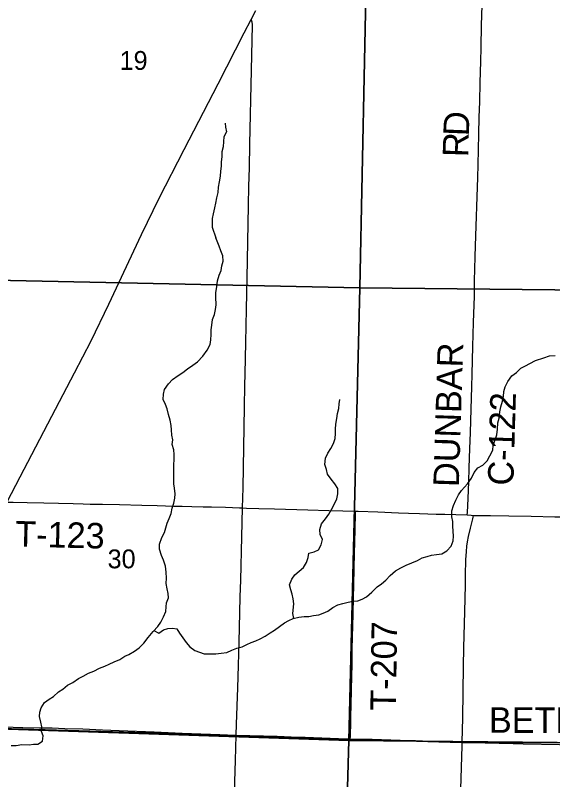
# Model space of a CAD drawing. Extents: x 1584893 to 1934202, y 663575 to 1091909.
# Drawn here: x 1777861 to 1784167, y 904934 to 913906 of the extents above; entities that cross this region are included whole.
import ezdxf

# ---------------------------------------------------------------- set-up
doc = ezdxf.new("R2010")
doc.units = 0
for name, color, linetype in [('GM_X_County_Road', 7, 'Continuous'), ('GM_X_County_Road_Text', 7, 'Continuous'), ('GM_X_Minor_River', 7, 'Continuous'), ('GM_X_Section', 7, 'Continuous'), ('GM_X_Section_Text', 7, 'Continuous'), ('GM_X_State_Route', 7, 'Continuous'), ('GM_X_Township', 7, 'Continuous'), ('GM_X_Township_Road', 7, 'Continuous'), ('GM_X_Township_Road_Text', 7, 'Continuous')]:
    doc.layers.add(name, color=color, linetype=linetype)

msp = doc.modelspace()

# ---------------------------------------------------------------- linework, layer by layer
at = {"layer": 'GM_X_County_Road'}
for points in [[(1783164.7, 908041.5), (1783166.1, 908070.2), (1783173.9, 908233.5), (1783181.1, 908430.1), (1783187.4, 908594), (1783195.5, 908823.4), (1783201.6, 909003.7), (1783205.7, 909151.2), (1783216, 909544.7), (1783220.3, 909692.2), (1783230.6, 910020.1), (1783237.7, 910298.8), (1783247.2, 910610.3), (1783249.5, 910790.7), (1783256.9, 911069.3), (1783262.5, 911200.3), (1783269.7, 911429.8), (1783280.2, 911774.1), (1783286.9, 912003.5), (1783292, 912151.1), (1783300.6, 912511.8), (1783305.7, 912708.5), (1783311.6, 912888.8), (1783317.5, 913118.4), (1783322.6, 913364.2), (1783325.5, 913528.2), (1783332.5, 913790.4), (1783339.3, 914019.9)], [(1780527.7, 908123.4), (1780533.2, 908358.4), (1780550.5, 909310), (1780555.8, 909562.5), (1780558.7, 909698.8), (1780566.5, 910064.6), (1780572.7, 910458.3), (1780581.4, 910819.1), (1780597.5, 911672.2), (1780601.6, 911901.7), (1780607.5, 912114.8), (1780613, 912393.7), (1780632.6, 913263), (1780642.7, 913788.2), (1780642.5, 913803.8), (1780641.8, 913811.7), (1780640.6, 913818.2), (1780638.3, 913826.3), (1780635.5, 913835.1), (1780631.1, 913847.5), (1780627.3, 913857.9)], [(1780452.8, 905456.3), (1780456.8, 905587.7), (1780470.4, 906014), (1780479.3, 906276.3), (1780486, 906555.2), (1780490.6, 906718.8), (1780500.5, 907079.4), (1780505.7, 907276.1), (1780519.7, 907784.4), (1780527.7, 908123.4)], [(1783106.2, 905376.6), (1783112.6, 905659.8), (1783120.5, 906267.1), (1783124.2, 906480.3), (1783133.9, 906906.9), (1783143.3, 907218.6), (1783145, 907333.6), (1783149.2, 907513.9), (1783154.3, 907612.1), (1783160.2, 907677.2), (1783167.1, 907725.7), (1783179.1, 907790), (1783201, 907885.9), (1783228.9, 907997.2), (1783238.9, 908036.5)], [(1776762.7, 905586.7), (1776948.6, 905580.9), (1777375, 905566.6), (1777949, 905548.7), (1778145.8, 905544.4), (1778293.5, 905541.5), (1778441, 905536.8), (1778654.1, 905530), (1778883.5, 905520.4), (1779080.3, 905512.4), (1779490.1, 905496.3), (1779818, 905482.6), (1780260.6, 905464.3), (1780440.9, 905456.7), (1780452.8, 905456.3)], [(1780376.1, 902828), (1780381.5, 903062.1), (1780396.4, 903570.5), (1780425.1, 904538.1), (1780443.4, 905161.3), (1780452.8, 905456.3)], [(1780452.8, 905456.3), (1780932.9, 905443.9), (1781180.7, 905435.2), (1781260.8, 905432.4), (1781752.8, 905415.6), (1781792.1, 905414.8)], [(1781792.1, 905414.8), (1782048, 905408.7), (1782376, 905398.2), (1782556.3, 905392.9), (1782638.2, 905390.2), (1782790.1, 905385.1), (1782848.8, 905383.1), (1783048.1, 905378.4), (1783106.2, 905376.6)], [(1783090.4, 904823), (1783105.1, 905331.6), (1783106.2, 905376.6)], [(1783106.2, 905376.6), (1783376.2, 905369.1), (1783704.2, 905358.8), (1783818.9, 905355.3), (1784245.3, 905347.5), (1784688.3, 905345.7), (1784901.5, 905347.7), (1785246, 905353), (1785475.7, 905357), (1785981.6, 905365), (1786017, 905365.5), (1786328.7, 905372.4), (1786558.5, 905372.2), (1786903.1, 905372.1), (1787083.1, 905370.1), (1787086.6, 905369.8)]]:
    msp.add_lwpolyline(points, dxfattribs=at)
at = {"layer": 'GM_X_Minor_River'}
for points in [[(1780321.6, 912641.7), (1780326.7, 912591.6), (1780337.8, 912539.4), (1780308.9, 912477.8), (1780302, 912425.9), (1780301, 912363.9), (1780284, 912304.1), (1780283, 912244.1), (1780278, 912184.2), (1780277.2, 912134.1), (1780270.3, 912078.2), (1780265.3, 912016.2), (1780252.2, 911950.4), (1780243.2, 911890.5), (1780236.2, 911826.6), (1780221.1, 911762.8), (1780208.1, 911699), (1780197.2, 911645.2), (1780182.1, 911575.4), (1780169.2, 911521.5), (1780172.4, 911471.4), (1780169.5, 911419.5), (1780213.8, 911293.1)], [(1779693.9, 909041.2), (1779690.7, 909093.4), (1779677.6, 909155.7), (1779658.6, 909222.1), (1779643.6, 909288.5), (1779624.4, 909338.9), (1779597.3, 909397.4), (1779598.2, 909459.5), (1779612.9, 909513.4), (1779657.8, 909578.8), (1779706.5, 909630.2), (1779773.1, 909679.3), (1779825.5, 909714.6), (1779880, 909757.9), (1779942.5, 909801), (1779997, 909838.3), (1780059.9, 909905.5), (1780110.8, 909976.9), (1780147.7, 910040.5), (1780156.5, 910096.4), (1780159.4, 910158.5), (1780160.2, 910214.6), (1780167, 910270.6), (1780175.9, 910334.6), (1780196.7, 910394.4), (1780211.6, 910454.3), (1780218.3, 910506.3), (1780213.6, 910596.6), (1780212.4, 910646.7), (1780227.4, 910722.6), (1780234.4, 910790.7), (1780253.3, 910854.5), (1780276.1, 910912.3), (1780284.9, 910966.3), (1780301.7, 911022.1), (1780294.6, 911082.4), (1780273.4, 911140.8), (1780252.3, 911197.2), (1780229.2, 911255.7), (1780213.8, 911293.1)], [(1779488, 906685.9), (1779545.5, 906654.7), (1779598, 906694), (1779650.1, 906709.2), (1779706.1, 906712.4), (1779757.9, 906705.6), (1779789.1, 906655), (1779828.2, 906598.4), (1779865.4, 906545.7), (1779910.5, 906492.9), (1779967.8, 906450), (1780023.4, 906431.1), (1780077.1, 906412.3), (1780212.8, 906410.2), (1780276.9, 906421.3), (1780342.9, 906428.3), (1780401.1, 906455.5), (1780461.4, 906476.7), (1780523.5, 906493.8), (1780575.8, 906523), (1780630.1, 906546.3), (1780682.2, 906563.5), (1780734.5, 906586.8), (1780792.9, 906620), (1780851.3, 906659.2), (1780901.7, 906688.5), (1780962.2, 906731.7), (1781020.7, 906774.9), (1781071.1, 906804.2), (1781121.3, 906825.5), (1781189.4, 906840.5), (1781249.4, 906849.6), (1781303.4, 906850.8), (1781359.4, 906862), (1781421.5, 906871.1), (1781471.6, 906888.4), (1781529.9, 906913.6), (1781588.4, 906956.8), (1781646.7, 906985.9), (1781704.9, 907003.1), (1781765, 907018.2), (1781821.1, 907031.4), (1781879.1, 907034.6), (1781929.2, 907053.8), (1781983.5, 907081.1), (1782044.3, 907136.3), (1782107, 907197.5), (1782157.5, 907232.8), (1782208, 907276.1), (1782258.7, 907329.4), (1782323.4, 907386.6), (1782383.8, 907421.8), (1782446.1, 907450.9), (1782514.5, 907479.9), (1782580.8, 907509), (1782635.1, 907538.2), (1782693.2, 907553.4), (1782745.4, 907568.6), (1782801.4, 907575.8), (1782867.4, 907586.8), (1782925.8, 907622), (1782976.5, 907675.4), (1782999.4, 907737.1), (1783004.2, 907793.2), (1782999, 907851.4), (1782995.9, 907909.5), (1782994.7, 907965.7), (1782983.5, 908019.9), (1782984.5, 908090.1), (1783001.4, 908153.9), (1783028.3, 908215.7), (1783061.1, 908277.3), (1783097.8, 908328.8), (1783166.8, 908407.9), (1783213.7, 908473.4), (1783244.6, 908539), (1783289.3, 908594.5), (1783345.7, 908627.7), (1783398.4, 908677), (1783429.1, 908734.7), (1783464.1, 908802.3), (1783466.9, 908856.3), (1783512.6, 908983.9), (1783519.6, 909049.9), (1783524.6, 909124), (1783537.4, 909177.9), (1783546.5, 909251.9), (1783559.3, 909311.8), (1783576.2, 909375.7), (1783589, 909433.7), (1783591.9, 909491.7), (1783610.6, 909543.5), (1783641.5, 909609.2), (1783688.3, 909672.6), (1783740.9, 909713.9), (1783793.5, 909765.2), (1783847.8, 909792.5), (1783898.1, 909819.8), (1783964.5, 909854.8), (1784060.8, 909887.4), (1784129.1, 909910.5)], [(1784129.1, 909910.5), (1784197, 909913.4)], [(1781130.2, 906827.5), (1781116.2, 906883.7), (1781129.8, 906999.7), (1781120.7, 907056), (1781109.5, 907110.2), (1781092.3, 907164.6), (1781079.1, 907220.9), (1781104, 907286.7), (1781140.7, 907338.2), (1781241.8, 907424.9), (1781276.6, 907484.5), (1781297.4, 907542.3), (1781306.2, 907594.3), (1781366.2, 907607.4), (1781420.5, 907630.6), (1781449.3, 907690.3), (1781466.2, 907752.2), (1781439.1, 907810.7), (1781434, 907872.9), (1781452.9, 907936.8), (1781501.7, 907996.2), (1781538.4, 908051.7), (1781571.1, 908105.3), (1781608.1, 908172.9), (1781634.9, 908232.6), (1781643.7, 908290.6), (1781644.6, 908352.7), (1781611.4, 908405.3), (1781566.3, 908462.1), (1781523.2, 908518.9), (1781512.1, 908575.1), (1781493, 908635.5), (1781502, 908709.6), (1781526.8, 908765.3), (1781563.6, 908822.9), (1781594.4, 908880.5), (1781613.2, 908938.3), (1781618, 908996.4), (1781618.8, 909050.5), (1781623.6, 909108.5), (1781632.5, 909172.5), (1781641.4, 909230.5), (1781658.2, 909292.4), (1781663, 909344.4), (1781667.7, 909396.4)], [(1777811.3, 905335.8), (1777871.2, 905336.9), (1777939.2, 905347.9), (1778023, 905342.7), (1778075.1, 905351.9), (1778127, 905351.1), (1778181.4, 905388.4), (1778188.3, 905450.4), (1778167.1, 905500.8), (1778173.9, 905556.8), (1778158.7, 905611.2), (1778145.6, 905675.5), (1778150.4, 905725.5), (1778165.1, 905779.4), (1778201.9, 905839), (1778256.4, 905880.3), (1778308.8, 905911.6), (1778369.5, 905964.8), (1778419.8, 905996.1), (1778474.4, 906043.4), (1778536.8, 906074.5), (1778601.4, 906123.7), (1778657.6, 906148.9), (1778720.1, 906184), (1778784.3, 906209.1), (1778850.7, 906242.2), (1778910.9, 906267.3), (1778961.2, 906288.6), (1779021.5, 906317.8), (1779087.8, 906346.9), (1779144.2, 906384.1), (1779194.5, 906405.4), (1779260.9, 906444.5), (1779313.4, 906481.8), (1779368.1, 906537.1), (1779419, 906604.5), (1779477.9, 906675.7), (1779532.6, 906731), (1779569.3, 906784.6), (1779600.2, 906846.2), (1779627, 906908), (1779631.8, 906962), (1779636.5, 907012), (1779657.3, 907069.8), (1779656.1, 907120), (1779642.9, 907174.3), (1779631.8, 907236.6), (1779634.7, 907300.6), (1779631.7, 907368.8), (1779622.8, 907441.1), (1779599.9, 907511.6), (1779576.7, 907566), (1779551.8, 907638.6), (1779552.7, 907700.7), (1779579.7, 907776.4), (1779610.5, 907836.1), (1779644.1, 907943.8), (1779664.9, 908001.6), (1779689.7, 908059.3), (1779702.6, 908123.3), (1779721.4, 908181.1), (1779734.2, 908239), (1779736.9, 908291.1), (1779727.9, 908357.4), (1779720.7, 908407.6), (1779721.4, 908461.7), (1779722.5, 908533.8), (1779721.2, 908583.9), (1779722, 908636), (1779724.7, 908686.1), (1779723.7, 908752.2), (1779720.4, 908804.4), (1779701.4, 908868.8), (1779708.2, 908924.8), (1779697, 908979.1), (1779693.9, 909041.2)]]:
    msp.add_lwpolyline(points, dxfattribs=at)
at = {"layer": 'GM_X_Section'}
for points in [[(1776623.4, 916198.9), (1782015, 916031.9), (1781905, 910708.6), (1776495.1, 910819.5)], [(1782015, 916031.9), (1787411.3, 915966.9), (1787237.4, 910654.4), (1781905, 910708.6)], [(1781905, 910708.6), (1781772.9, 905394.9), (1776367.5, 905575.7), (1776495.1, 910819.5)], [(1787237.4, 910654.4), (1787071.3, 905344.9), (1781772.9, 905394.9), (1781905, 910708.6)], [(1776367.5, 905575.7), (1781772.9, 905394.9), (1781625.2, 900145.3), (1776353.6, 900299.2), (1776548.3, 900915.7), (1776676.3, 901176.8), (1776750.2, 901424.3), (1776771.5, 901594.2), (1776800.4, 902252), (1776798.3, 902502.1), (1776717.9, 902982.7), (1776549.7, 903742.1), (1776423.6, 904265.1), (1776354.8, 904955.7), (1776143.5, 905573.4)], [(1787071.3, 905344.9), (1786953.9, 900673.1), (1784373.6, 900418.5), (1781625.2, 900145.3), (1781772.9, 905394.9)]]:
    msp.add_lwpolyline(points, close=True, dxfattribs=at)
at = {"layer": 'GM_X_State_Route'}
msp.add_lwpolyline([(1776673.6, 906128.5), (1776954.6, 906658.7), (1777122.2, 906978.2), (1777760.9, 908190.5), (1777764.6, 908197.3), (1777916.6, 908487.9), (1778053.3, 908749.6), (1778289.9, 909199.8), (1778557.3, 909707.8), (1778752.3, 910087.2), (1778958.3, 910516.1), (1779343.6, 911332), (1779549.6, 911760.7), (1779841.4, 912329.9), (1780239.9, 913102.8), (1780547.1, 913701), (1780627.3, 913857.9), (1780681.5, 913964)], dxfattribs=at)
at = {"layer": 'GM_X_Township'}
for points in [[(1787078.2, 905366.1), (1783095.2, 905371.3), (1781776.1, 905410.9), (1780447.2, 905454.6), (1776625.9, 905568.3)], [(1776625.9, 905568.3), (1780447.2, 905454.6), (1781776.1, 905410.9), (1783095.2, 905371.3), (1787078.2, 905366.1)]]:
    msp.add_lwpolyline(points, dxfattribs=at)
at = {"layer": 'GM_X_Township_Road'}
for points in [[(1777760.9, 908190.5), (1777836.9, 908190.1), (1778000.7, 908187.7), (1778197.5, 908183.6), (1778541.7, 908174.2), (1778656.3, 908170.9), (1778738.1, 908169.3), (1778885.6, 908166.4), (1779082.2, 908163), (1779344.2, 908155.6), (1779524.5, 908151.7), (1779721.1, 908146.4), (1779819.4, 908144.5), (1779934, 908141.8), (1780064.9, 908137.6), (1780163.2, 908135.7), (1780327.1, 908131.8), (1780491, 908124.7), (1780527.7, 908123.4)], [(1780527.7, 908123.4), (1780572.8, 908121.5), (1780720.3, 908119.2), (1780900.5, 908113.8), (1781293.7, 908102.6), (1781539.6, 908095.9), (1781703.5, 908090.5), (1781852.5, 908085.5)], [(1781792.1, 905414.8), (1781792.9, 905439.6), (1781798.5, 905618), (1781799.7, 905685.1), (1781801.7, 905799.8), (1781806.4, 905996.5), (1781812.1, 906291.6), (1781815.1, 906455.5), (1781818.1, 906619.5), (1781821.1, 906734.2), (1781824.5, 906881.7), (1781828.6, 907078.4), (1781832.1, 907209.5), (1781837.1, 907422.7), (1781839.7, 907586.6), (1781847.5, 907865.2), (1781852, 908061.9), (1781852.5, 908085.5)], [(1781852.5, 908085.5), (1781883.6, 908084.6), (1782113.1, 908077.6), (1782358.8, 908067.6), (1782473.4, 908064.2), (1782604.5, 908060.6), (1782801, 908052.9), (1782899.3, 908050.2), (1783030.4, 908046.8), (1783161.4, 908041.7), (1783164.7, 908041.5)], [(1783164.7, 908041.5), (1783210.5, 908038.1), (1783238.9, 908036.5)], [(1783238.9, 908036.5), (1783276.5, 908036.2), (1783438.6, 908034.3), (1783652.6, 908031.5), (1783914.8, 908026), (1784193.5, 908021), (1784422.9, 908019.5), (1784701.6, 908018.5), (1784947.4, 908021.1), (1785111.3, 908024.1), (1785275.2, 908028.9), (1785521.1, 908032), (1785799.8, 908036.2), (1786062.1, 908038.6), (1786357.2, 908037.8), (1786668.8, 908036.3), (1786881.9, 908034.9), (1787114.8, 908032.3), (1787152.2, 908031.5), (1787165.7, 908031.1)]]:
    msp.add_lwpolyline(points, dxfattribs=at)

# ---------------------------------------------------------------- texts
at = {"layer": 'GM_X_County_Road_Text'}
for s, rotation, p in [('D', 87.81014, (1783182.1, 912484.4)), ('R', 88.39172, (1783175.3, 912238.9)), ('DUNBAR', 88.22477, (1783065.2, 908366.6)), ('C-122', 88.34837, (1783704.3, 908383.6)), ('BETHLEHEM', 359.88978, (1783418.4, 905485))]:
    msp.add_text(s, height=300, rotation=rotation, dxfattribs=at).set_placement(p)
at = {"layer": 'GM_X_Section_Text'}
for s, p in [('19', (1779084.7, 913265.5)), ('30', (1778943.9, 907415.7))]:
    msp.add_text(s, height=221, rotation=0.00001, dxfattribs=at).set_placement(p)
at = {"layer": 'GM_X_Township_Road_Text'}
for s, rotation, p in [('T-123', 358.60424, (1777858.2, 907671.5)), ('T-207', 89.15799, (1782326.7, 905743.3))]:
    msp.add_text(s, height=300, rotation=rotation, dxfattribs=at).set_placement(p)

doc.saveas('drawing.dxf')
